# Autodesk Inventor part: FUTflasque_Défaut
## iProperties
Shininess: 64.0
Length Units: 11269
Angle Units: 11279
Time Units: 11290
Mass Units: 11283
Length Display Precision: 3
Angle Display Precision: 2
Compacted: True
Part Number: FUTflasque_Défaut
Document SubType Name: Modeling
Created: 2006-11
Material: Par défaut
Designer: profs_sti
Density: 0.0
Volumn: 0.0
Area: 0.0
PropertySet Name: Model Information
Control State: 0
Master: False
Checked Out: False
Author: profs_sti
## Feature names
1. Base1
